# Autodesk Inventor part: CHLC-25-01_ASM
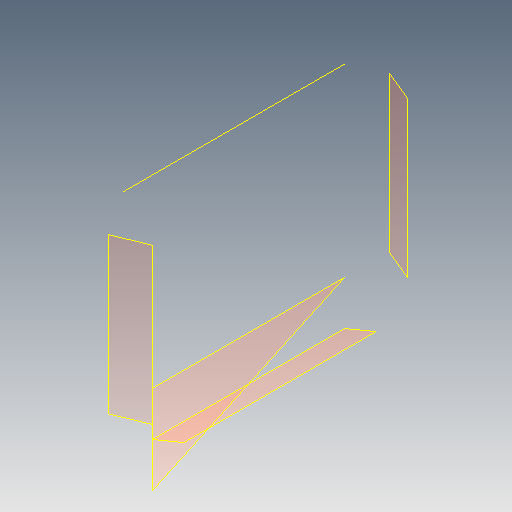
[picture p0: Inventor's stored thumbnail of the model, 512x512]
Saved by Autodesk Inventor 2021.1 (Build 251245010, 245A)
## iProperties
Created: 2021-05
Part Number: CHLC-25-01_ASM
Material: Ogólny
Document SubType Name: Modeling
Designer: user
Density: 1 g/cm^3
Appearance: Domyślna
Author: user
Revision Number: ÈÎºÎ
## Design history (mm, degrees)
feature "Złożony1"
body "Srf1"
